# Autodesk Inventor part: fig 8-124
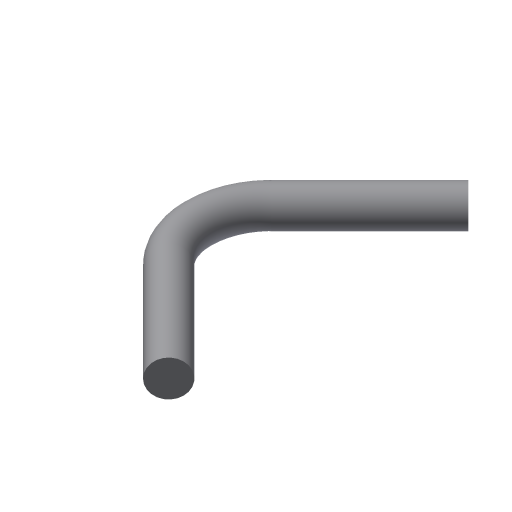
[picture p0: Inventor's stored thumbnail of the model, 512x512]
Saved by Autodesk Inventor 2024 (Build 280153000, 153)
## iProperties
Created: 2007-02
Part Number: fig 8-124
Document SubType Name: Modeling
Designer: Administrator
Density: 1 g/cm^3
Material: Generic
Appearance: Default
Author: Administrator
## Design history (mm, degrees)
sketch "Sketch2"
  geometry: C1 r 5 at (0, 0); 1 further point
  constraints: 1 centre point, 1 coincident, 1 other
  dimensions: "d0" = 10 diameter of C1
extrude "Extrusion1" new body sketch "Sketch2" stored distance "d1" = 100; taper "d2" = 0 deg
workplane "Work Plane1"
sketch "Sketch3"
  geometry: L1 (0, 11)-(0, -8)
  constraints: 2 end point, 1 vertical
feature "Bend Part2" sketch "Sketch3" dims "d5" = 15, "d6" = 90 deg
body "Solid1"
node "Sketch1"
